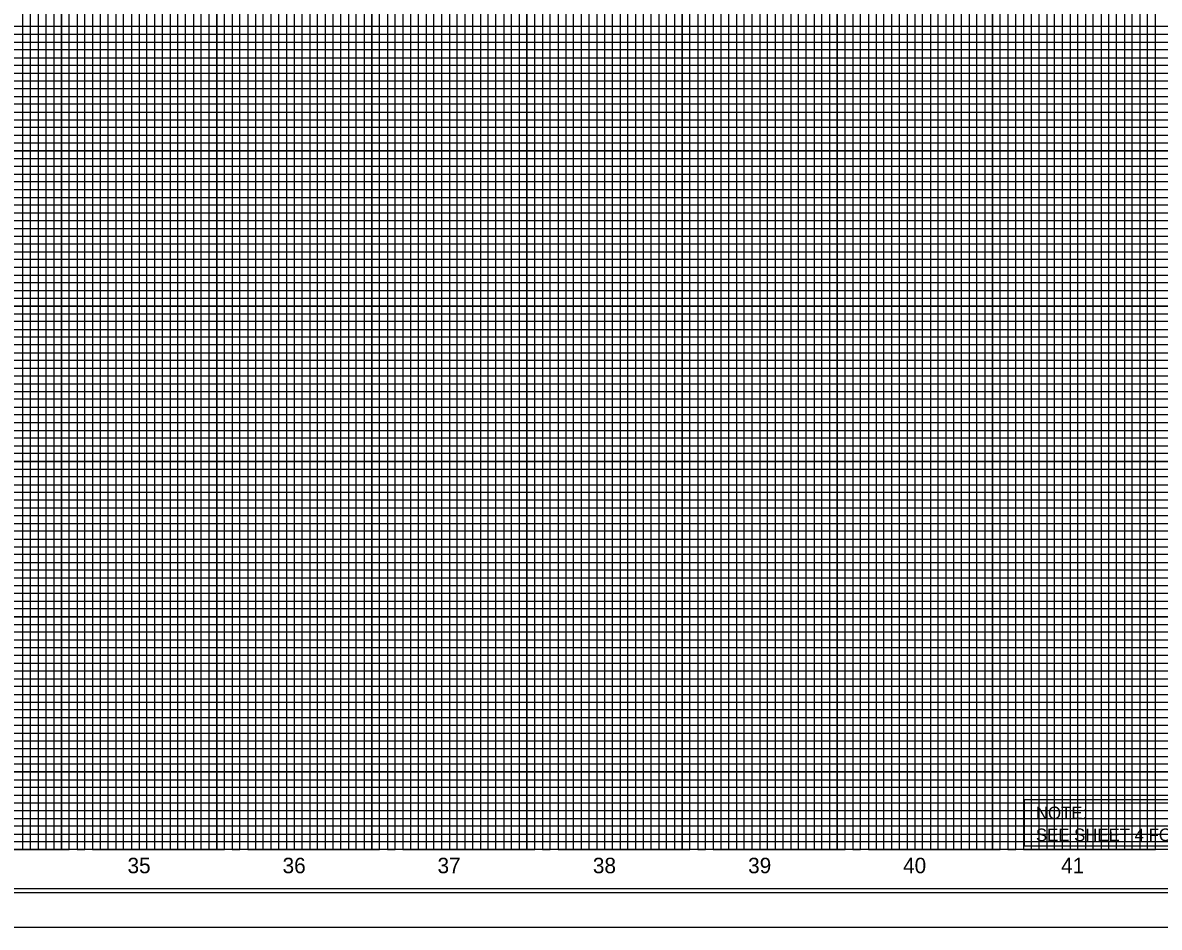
# Model space of a CAD drawing. Extents: x 2195312 to 2197193, y 76953 to 78053.
# Drawn here: x 2196054 to 2196786, y 76953 to 77535 of the extents above; entities that cross this region are included whole.
import ezdxf

# ---------------------------------------------------------------- set-up
doc = ezdxf.new("R2010")
doc.units = 0
for name, color, linetype in [('Exist Structure Minor Culvert Topo', 7, 'Continuous'), ('Old_Level_2', 7, 'Continuous'), ('Old_Level_3', 7, 'Continuous'), ('Prop North Arrow NAD83 for Plan Sheets CELL', 7, 'Continuous'), ('Scratch_Level_0', 7, 'Continuous'), ('Sheet Cutting Line CELL', 7, 'Continuous'), ('Sheet Data Field CELL', 7, 'Continuous'), ('Sheet Plan CELL', 7, 'Continuous'), ('Sheet Plot Border Inside CELL', 7, 'Continuous'), ('Sheet Plot Border Outside CELL', 7, 'Continuous'), ('Sheet Sticker Incomplete CELL', 7, 'Continuous'), ('Sheet Sticker Preliminary CELL', 7, 'Continuous')]:
    doc.layers.add(name, color=color, linetype=linetype)

msp = doc.modelspace()

# ---------------------------------------------------------------- linework, layer by layer
at = {"layer": 'Exist Structure Minor Culvert Topo'}
msp.add_lwpolyline([(2195528.73, 77352.66), (2196928.73, 77352.66), (2196928.73, 77002.66), (2195528.73, 77002.66)], close=True, dxfattribs=at)
at = {"layer": 'Old_Level_2'}
msp.add_lwpolyline([(2196991.23, 78030.21), (2195324.73, 78030.21), (2195324.73, 76975.11), (2196991.23, 76975.11)], close=True, dxfattribs=at)
at = {"layer": 'Old_Level_3'}
msp.add_lwpolyline([(2196699.27, 77034.85), (2196926.09, 77034.85), (2196926.09, 77004.85), (2196699.27, 77004.85)], close=True, dxfattribs=at)
at = {"layer": 'Scratch_Level_0'}
for points in [[(2195528.73, 77702.66), (2196928.73, 77702.66), (2196928.73, 77352.66), (2195528.73, 77352.66)], [(2195528.73, 77702.66), (2196928.73, 77702.66), (2196928.73, 77352.66), (2195528.73, 77352.66)], [(2195528.73, 77402.66), (2196928.73, 77402.66), (2196928.73, 77052.66), (2195528.73, 77052.66)]]:
    msp.add_lwpolyline(points, close=True, dxfattribs=at)
at = {"layer": 'Sheet Cutting Line CELL'}
for points in [[(2196028.73, 77002.66), (2196078.73, 77002.66), (2196078.73, 78027.66)], [(2196128.73, 78027.66), (2196128.73, 77002.66), (2196178.73, 77002.66), (2196178.73, 78027.66)], [(2196228.73, 78027.66), (2196228.73, 77002.66), (2196278.73, 77002.66), (2196278.73, 78027.66)], [(2196328.73, 78027.66), (2196328.73, 77002.66), (2196378.73, 77002.66), (2196378.73, 78027.66)], [(2196428.73, 78027.66), (2196428.73, 77002.66), (2196478.73, 77002.66), (2196478.73, 78027.66)], [(2196528.73, 78027.66), (2196528.73, 77002.66), (2196578.73, 77002.66), (2196578.73, 78027.66)], [(2196628.73, 78027.66), (2196628.73, 77002.66), (2196678.73, 77002.66), (2196678.73, 78027.66)], [(2196728.73, 78027.66), (2196728.73, 77002.66), (2196778.73, 77002.66), (2196778.73, 78027.66)], [(2196978.73, 77452.66), (2195478.73, 77452.66), (2195478.73, 77502.66), (2196978.73, 77502.66)], [(2196978.73, 77352.66), (2195478.73, 77352.66), (2195478.73, 77402.66), (2196978.73, 77402.66)], [(2196978.73, 77252.66), (2195478.73, 77252.66), (2195478.73, 77302.66), (2196978.73, 77302.66)], [(2196978.73, 77152.66), (2195478.73, 77152.66), (2195478.73, 77202.66), (2196978.73, 77202.66)], [(2196978.73, 77052.66), (2195478.73, 77052.66), (2195478.73, 77102.66), (2196978.73, 77102.66)]]:
    msp.add_lwpolyline(points, dxfattribs=at)
at = {"layer": 'Sheet Data Field CELL'}
for points in [[(2196058.73, 77002.66), (2196058.73, 78027.66)], [(2196063.73, 78027.66), (2196063.73, 77002.66), (2196068.73, 77002.66), (2196068.73, 78027.66)], [(2196073.73, 78027.66), (2196073.73, 77002.66), (2196083.73, 77002.66), (2196083.73, 78027.66)], [(2196088.73, 78027.66), (2196088.73, 77002.66), (2196088.73, 77002.66), (2196093.73, 77002.66), (2196093.73, 78027.66)], [(2196098.73, 78027.66), (2196098.73, 77002.66), (2196108.73, 77002.66), (2196108.73, 78027.66)], [(2196113.73, 78027.66), (2196113.73, 77002.66), (2196118.73, 77002.66), (2196118.73, 78027.66)], [(2196123.73, 78027.66), (2196123.73, 77002.66), (2196133.73, 77002.66), (2196133.73, 78027.66)], [(2196138.73, 78027.66), (2196138.73, 77002.66), (2196143.73, 77002.66), (2196143.73, 78027.66)], [(2196148.73, 78027.66), (2196148.73, 77002.66), (2196158.73, 77002.66), (2196158.73, 78027.66)], [(2196163.73, 78027.66), (2196163.73, 77002.66), (2196168.73, 77002.66), (2196168.73, 78027.66)], [(2196173.73, 78027.66), (2196173.73, 77002.66), (2196183.73, 77002.66), (2196183.73, 78027.66)], [(2196188.73, 78027.66), (2196188.73, 77002.66), (2196193.73, 77002.66), (2196193.73, 78027.66)], [(2196198.73, 78027.66), (2196198.73, 77002.66), (2196208.73, 77002.66), (2196208.73, 78027.66)], [(2196213.73, 78027.66), (2196213.73, 77002.66), (2196218.73, 77002.66), (2196218.73, 78027.66)], [(2196223.73, 78027.66), (2196223.73, 77002.66), (2196233.73, 77002.66), (2196233.73, 78027.66)], [(2196238.73, 78027.66), (2196238.73, 77002.66)], [(2196238.73, 77002.66), (2196243.73, 77002.66), (2196243.73, 78027.06)], [(2196248.73, 78027.06), (2196248.73, 77002.66), (2196258.73, 77002.66), (2196258.73, 78027.66)], [(2196263.73, 78027.66), (2196263.73, 77002.66), (2196268.73, 77002.66), (2196268.73, 78027.66)], [(2196273.73, 78027.66), (2196273.73, 77002.66), (2196283.73, 77002.66), (2196283.73, 78027.66)], [(2196288.73, 78027.66), (2196288.73, 77002.66), (2196293.73, 77002.66), (2196293.73, 78027.66)], [(2196298.73, 78027.66), (2196298.73, 77002.66), (2196308.73, 77002.66), (2196308.73, 78027.66)], [(2196313.73, 78027.66), (2196313.73, 77002.66), (2196318.73, 77002.66), (2196318.73, 78027.66)], [(2196323.73, 78027.66), (2196323.73, 77002.66), (2196333.73, 77002.66), (2196333.73, 78027.66)], [(2196338.73, 78027.66), (2196338.73, 77002.66), (2196343.73, 77002.66), (2196343.73, 78027.66)], [(2196348.73, 78027.66), (2196348.73, 77002.66), (2196358.73, 77002.66), (2196358.73, 78027.66)], [(2196363.73, 78027.66), (2196363.73, 77002.66), (2196368.73, 77002.66), (2196368.73, 78027.66)], [(2196373.73, 78027.66), (2196373.73, 77002.66), (2196383.73, 77002.66), (2196383.73, 78027.66)], [(2196388.73, 78027.66), (2196388.73, 77002.66), (2196393.73, 77002.66), (2196393.73, 78027.66)], [(2196398.73, 78027.66), (2196398.73, 77002.66), (2196408.73, 77002.66), (2196408.73, 78027.66)], [(2196413.73, 78027.66), (2196413.73, 77002.66), (2196418.73, 77002.66), (2196418.73, 78027.66)], [(2196423.73, 78027.66), (2196423.73, 77002.66), (2196433.73, 77002.66), (2196433.73, 78027.66)], [(2196438.73, 78027.66), (2196438.73, 77002.66), (2196443.73, 77002.66), (2196443.73, 78027.66)], [(2196448.73, 78027.66), (2196448.73, 77002.66), (2196458.73, 77002.66), (2196458.73, 78027.66)], [(2196463.73, 78027.66), (2196463.73, 77002.66), (2196468.73, 77002.66), (2196468.73, 78027.66)], [(2196473.73, 78027.66), (2196473.73, 77002.66), (2196483.73, 77002.66), (2196483.73, 78027.66)], [(2196488.73, 78027.66), (2196488.73, 77002.66), (2196493.73, 77002.66), (2196493.73, 78027.66)], [(2196498.73, 78027.66), (2196498.73, 77002.66), (2196508.73, 77002.66), (2196508.73, 78027.66)], [(2196513.73, 78027.66), (2196513.73, 77002.66), (2196518.73, 77002.66), (2196518.73, 78027.66)], [(2196523.73, 78027.66), (2196523.73, 77002.66), (2196533.73, 77002.66), (2196533.73, 78027.66)], [(2196538.73, 78027.66), (2196538.73, 77002.66), (2196543.73, 77002.66), (2196543.73, 78027.66)], [(2196548.73, 78027.66), (2196548.73, 77002.66)], [(2196548.73, 77002.66), (2196558.73, 77002.66), (2196558.73, 78027.66)], [(2196563.73, 78027.66), (2196563.73, 77002.66), (2196568.73, 77002.66), (2196568.73, 78027.66)], [(2196573.73, 78027.66), (2196573.73, 77002.66), (2196583.73, 77002.66), (2196583.73, 78027.66)], [(2196588.73, 78027.66), (2196588.73, 77002.66), (2196593.73, 77002.66), (2196593.73, 78027.66)], [(2196598.73, 78027.66), (2196598.73, 77002.66), (2196608.73, 77002.66), (2196608.73, 78027.66)], [(2196613.73, 78027.66), (2196613.73, 77002.66), (2196618.73, 77002.66), (2196618.73, 78027.66)], [(2196623.73, 78027.66), (2196623.73, 77002.66), (2196633.73, 77002.66), (2196633.73, 78027.66)], [(2196638.73, 78027.66), (2196638.73, 77002.66), (2196643.73, 77002.66), (2196643.73, 78027.66)], [(2196648.73, 78027.66), (2196648.73, 77002.66), (2196658.73, 77002.66), (2196658.73, 78027.66)], [(2196663.73, 78027.66), (2196663.73, 77002.66), (2196668.73, 77002.66), (2196668.73, 78027.66)], [(2196673.73, 78027.66), (2196673.73, 77002.66), (2196683.73, 77002.66), (2196683.73, 78027.66)], [(2196688.73, 78027.66), (2196688.73, 77002.66), (2196693.73, 77002.66), (2196693.73, 78027.66)], [(2196698.73, 78027.66), (2196698.73, 77002.66), (2196708.73, 77002.66), (2196708.73, 78027.66)], [(2196713.73, 78027.66), (2196713.73, 77002.66), (2196718.73, 77002.66), (2196718.73, 78027.66)], [(2196723.73, 78027.66), (2196723.73, 77002.66), (2196733.73, 77002.66), (2196733.73, 78027.66)], [(2196738.73, 78027.66), (2196738.73, 77002.66), (2196743.73, 77002.66), (2196743.73, 78027.66)], [(2196748.73, 78027.66), (2196748.73, 77002.66), (2196758.73, 77002.66), (2196758.73, 78027.66)], [(2196763.73, 78027.66), (2196763.73, 77002.66), (2196768.73, 77002.66), (2196768.73, 78027.66)], [(2196773.73, 78027.66), (2196773.73, 77002.66), (2196783.73, 77002.66), (2196783.73, 77866.61)], [(2196928.73, 77532.66), (2195528.73, 77532.66), (2195528.73, 77522.66), (2196928.73, 77522.66)], [(2196928.73, 77517.66), (2195528.73, 77517.66), (2195528.73, 77512.66), (2196928.73, 77512.66)], [(2196928.73, 77507.66), (2195528.73, 77507.66)], [(2195528.73, 77497.66), (2196928.73, 77497.66)], [(2196928.73, 77492.66), (2195528.73, 77492.66), (2195528.73, 77487.66), (2196928.73, 77487.66)], [(2196928.73, 77482.66), (2195528.73, 77482.66), (2195528.73, 77472.66), (2196928.73, 77472.66)], [(2196928.73, 77467.66), (2195528.73, 77467.66), (2195528.73, 77462.66), (2196928.73, 77462.66)], [(2196928.73, 77457.66), (2195528.73, 77457.66), (2195528.73, 77447.66), (2196928.73, 77447.66)], [(2196928.73, 77442.66), (2195528.73, 77442.66), (2195528.73, 77437.66), (2196928.73, 77437.66)], [(2196928.73, 77432.66), (2195528.73, 77432.66), (2195528.73, 77422.66), (2196928.73, 77422.66)], [(2196928.73, 77417.66), (2195528.73, 77417.66), (2195528.73, 77412.66), (2196928.73, 77412.66)], [(2196928.73, 77407.66), (2195528.73, 77407.66), (2195528.73, 77397.66), (2196928.73, 77397.66)], [(2196928.73, 77392.66), (2195528.73, 77392.66), (2195528.73, 77387.66), (2196928.73, 77387.66)], [(2196928.73, 77382.66), (2195528.73, 77382.66), (2195528.73, 77372.66), (2196928.73, 77372.66)], [(2196928.73, 77367.66), (2195528.73, 77367.66), (2195528.73, 77362.66), (2196928.73, 77362.66)], [(2196928.73, 77357.66), (2195528.73, 77357.66), (2195528.73, 77347.66), (2196928.73, 77347.66)], [(2196928.73, 77342.66), (2195528.73, 77342.66), (2195528.73, 77337.66), (2196928.73, 77337.66)], [(2196928.73, 77332.66), (2195528.73, 77332.66), (2195528.73, 77322.66), (2196928.73, 77322.66)], [(2196928.73, 77317.66), (2195528.73, 77317.66), (2195528.73, 77312.66), (2196928.73, 77312.66)], [(2196928.73, 77307.66), (2195528.73, 77307.66), (2195528.73, 77297.66), (2196928.73, 77297.66)], [(2196928.73, 77292.66), (2195528.73, 77292.66), (2195528.73, 77287.66), (2196928.73, 77287.66)], [(2196928.73, 77282.66), (2195528.73, 77282.66), (2195528.73, 77272.66), (2196928.73, 77272.66)], [(2196928.73, 77267.66), (2195528.73, 77267.66), (2195528.73, 77262.66), (2196928.73, 77262.66)], [(2196928.73, 77257.66), (2195528.73, 77257.66), (2195528.73, 77247.66), (2196928.73, 77247.66)], [(2196928.73, 77242.66), (2195528.73, 77242.66), (2195528.73, 77237.66), (2196928.73, 77237.66)], [(2196928.73, 77232.66), (2195528.73, 77232.66), (2195528.73, 77222.66), (2196928.73, 77222.66)], [(2196928.73, 77217.66), (2195528.73, 77217.66), (2195528.73, 77212.66), (2196928.73, 77212.66)], [(2196928.73, 77207.66), (2195528.73, 77207.66)], [(2195528.73, 77197.66), (2196928.73, 77197.66)], [(2196928.73, 77192.66), (2195528.73, 77192.66), (2195528.73, 77187.66), (2196928.73, 77187.66)], [(2196928.73, 77182.66), (2195528.73, 77182.66)], [(2195528.73, 77172.66), (2196928.73, 77172.66)], [(2196928.73, 77167.66), (2195528.73, 77167.66), (2195528.73, 77162.66), (2196928.73, 77162.66)], [(2196928.73, 77157.66), (2195528.73, 77157.66), (2195528.73, 77147.66), (2196928.73, 77147.66)], [(2196928.73, 77142.66), (2195528.73, 77142.66), (2195528.73, 77137.66), (2196928.73, 77137.66)], [(2196928.73, 77132.66), (2195528.73, 77132.66), (2195528.73, 77122.66), (2196928.73, 77122.66)], [(2196928.73, 77117.66), (2195528.73, 77117.66), (2195528.73, 77112.66), (2196928.73, 77112.66)], [(2196928.73, 77107.66), (2195528.73, 77107.66), (2195528.73, 77097.66), (2196928.73, 77097.66)], [(2196928.73, 77092.66), (2195528.73, 77092.66), (2195528.73, 77087.66), (2196928.73, 77087.66)], [(2196928.73, 77082.66), (2195528.73, 77082.66), (2195528.73, 77072.66), (2196928.73, 77072.66)], [(2196928.73, 77067.66), (2195528.73, 77067.66), (2195528.73, 77062.66), (2196928.73, 77062.66)], [(2196928.73, 77057.66), (2195528.73, 77057.66), (2195528.73, 77047.66), (2196928.73, 77047.66)], [(2196928.73, 77042.66), (2195528.73, 77042.66), (2195528.73, 77037.66), (2196928.73, 77037.66)], [(2196928.73, 77032.66), (2195528.73, 77032.66), (2195528.73, 77022.66), (2196928.73, 77022.66)], [(2196928.73, 77017.66), (2195528.73, 77017.66), (2195528.73, 77012.66), (2196928.73, 77012.66)], [(2196928.73, 77007.66), (2195528.73, 77007.66)]]:
    msp.add_lwpolyline(points, dxfattribs=at)
at = {"layer": 'Sheet Plan CELL'}
msp.add_lwpolyline([(2196995.73, 78052.66), (2195311.73, 78052.66), (2195311.73, 76952.66), (2196995.73, 76952.66)], close=True, dxfattribs=at)
at = {"layer": 'Sheet Plot Border Inside CELL'}
for p, q in [((2195478.73, 77352.66), (2196978.73, 77352.66)), ((2196978.73, 77002.66), (2195478.73, 77002.66))]:
    msp.add_line(p, q, dxfattribs=at)
msp.add_lwpolyline([(2196978.73, 78027.66), (2195478.73, 78027.66), (2195478.73, 76977.66), (2196978.73, 76977.66)], close=True, dxfattribs=at)
at = {"layer": 'Sheet Plot Border Outside CELL'}
for points in [[(2196003.73, 77002.66), (2196053.73, 77002.66), (2196053.73, 78027.66)], [(2196103.73, 78027.66), (2196103.73, 77002.66), (2196153.73, 77002.66), (2196153.73, 78027.66)], [(2196203.73, 78027.66), (2196203.73, 77002.66), (2196253.73, 77002.66), (2196253.73, 78027.66)], [(2196303.73, 78027.66), (2196303.73, 77002.66), (2196353.73, 77002.66), (2196353.73, 78027.66)], [(2196403.73, 78027.66), (2196403.73, 77002.66), (2196453.73, 77002.66), (2196453.73, 78027.66)], [(2196503.73, 78027.66), (2196503.73, 77002.66), (2196553.73, 77002.66), (2196553.73, 78027.66)], [(2196603.73, 78027.66), (2196603.73, 77002.66), (2196653.73, 77002.66), (2196653.73, 78027.66)], [(2196703.73, 78027.66), (2196703.73, 77002.66), (2196753.73, 77002.66), (2196753.73, 78027.66)], [(2196978.73, 77527.66), (2195478.73, 77527.66), (2195478.73, 77477.66), (2196978.73, 77477.66)], [(2196978.73, 77427.66), (2195478.73, 77427.66), (2195478.73, 77377.66), (2196978.73, 77377.66)], [(2196978.73, 77327.66), (2195478.73, 77327.66), (2195478.73, 77277.66), (2196978.73, 77277.66)], [(2196978.73, 77227.66), (2195478.73, 77227.66), (2195478.73, 77177.66), (2196978.73, 77177.66)], [(2196978.73, 77127.66), (2195478.73, 77127.66), (2195478.73, 77077.66), (2196978.73, 77077.66)], [(2196978.73, 77027.66), (2195478.73, 77027.66)]]:
    msp.add_lwpolyline(points, dxfattribs=at)
at = {"layer": 'Sheet Sticker Incomplete CELL'}
msp.add_line((2195311.73, 76952.66), (2196995.73, 76952.66), dxfattribs=at)
at = {"layer": 'Sheet Sticker Preliminary CELL'}
for p, q in [((2196078.73, 78027.66), (2196078.73, 77002.66)), ((2196128.73, 78027.66), (2196128.73, 77002.66)), ((2196178.73, 78027.66), (2196178.73, 77002.66)), ((2196228.73, 78027.66), (2196228.73, 77002.66)), ((2196278.73, 78027.66), (2196278.73, 77002.66)), ((2196328.73, 78027.66), (2196328.73, 77002.66)), ((2196378.73, 78027.66), (2196378.73, 77002.66)), ((2196428.73, 78027.66), (2196428.73, 77002.66)), ((2196478.73, 78027.66), (2196478.73, 77002.66)), ((2196528.73, 78027.66), (2196528.73, 77002.66)), ((2196578.73, 78027.66), (2196578.73, 77002.66)), ((2196628.73, 78027.66), (2196628.73, 77002.66)), ((2196678.73, 78027.66), (2196678.73, 77002.66)), ((2196728.73, 78027.66), (2196728.73, 77002.66)), ((2196778.73, 77002.66), (2196778.73, 77890.11)), ((2195478.73, 77502.66), (2196978.73, 77502.66)), ((2195478.73, 77452.66), (2196978.73, 77452.66)), ((2195478.73, 77402.66), (2196978.73, 77402.66)), ((2195478.73, 77352.66), (2196978.73, 77352.66)), ((2195478.73, 77302.66), (2196978.73, 77302.66)), ((2195478.73, 77252.66), (2196978.73, 77252.66)), ((2195478.73, 77202.66), (2196978.73, 77202.66)), ((2195478.73, 77152.66), (2196978.73, 77152.66)), ((2195478.73, 77102.66), (2196978.73, 77102.66)), ((2195478.73, 77052.66), (2196978.73, 77052.66))]:
    msp.add_line(p, q, dxfattribs=at)

# ---------------------------------------------------------------- texts
at = {"layer": 'Exist Structure Minor Culvert Topo'}
for s, height, p in [('NOTE:', 8.077, (2196706.72, 77022.27)), ('SEE SHEET 4 FOR -L- PLAN', 8.0769, (2196706.73, 77008.13))]:
    msp.add_text(s, height=height, rotation=0.02303, dxfattribs=at).set_placement(p)
at = {"layer": 'Prop North Arrow NAD83 for Plan Sheets CELL'}
for s, p in [('35', (2196121.27, 76987.43)), ('36', (2196221.21, 76987.43)), ('37', (2196321.07, 76987.43)), ('38', (2196421.2, 76987.43)), ('39', (2196521.24, 76987.43)), ('40', (2196621.12, 76987.43)), ('41', (2196722.95, 76987.43))]:
    msp.add_text(s, height=10, dxfattribs=at).set_placement(p)

doc.saveas('drawing.dxf')
